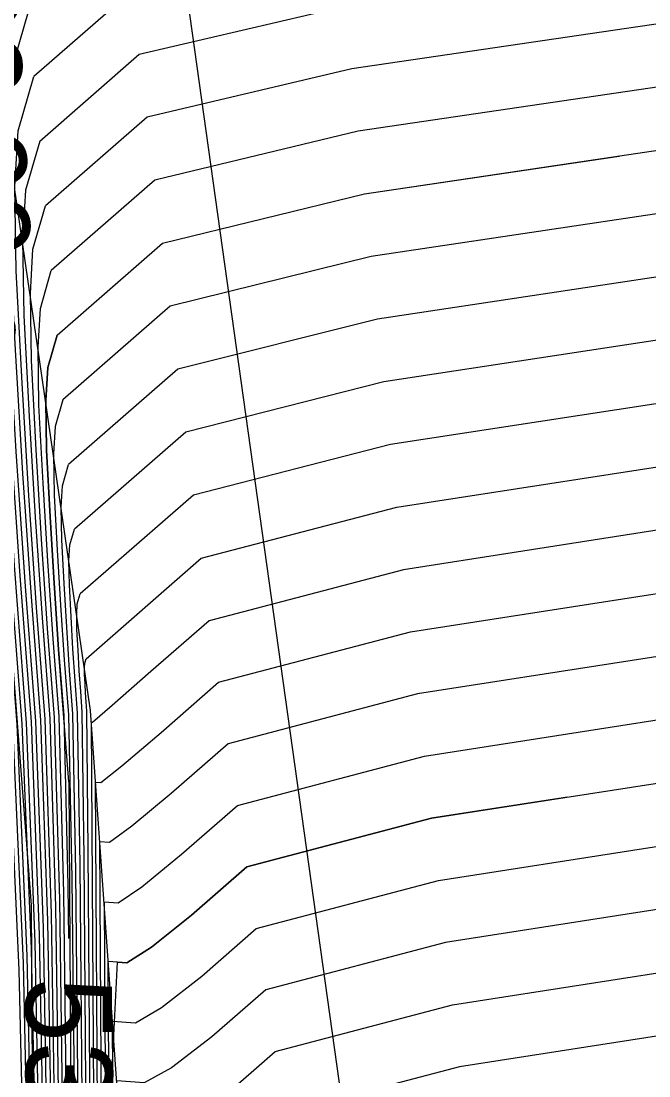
# Model space of a CAD drawing. Extents: x -866683 to -866410, y -1041951 to -1040252.
# Drawn here: x -866462.047 to -866459.87, y -1041930.1 to -1041926.441 of the extents above; entities that cross this region are included whole.
import ezdxf

# ---------------------------------------------------------------- set-up
doc = ezdxf.new("R2010")
doc.units = 0
for name, color, linetype in [('BODY', 7, 'Continuous'), ('BODY_2016', 7, 'Continuous'), ('BREAKLINE', 7, 'Continuous'), ('V-HL', 7, 'Continuous'), ('V-VEDL', 7, 'Continuous'), ('V_po_cm', 7, 'Continuous')]:
    doc.layers.add(name, color=color, linetype=linetype)

msp = doc.modelspace()

# ---------------------------------------------------------------- linework, layer by layer
at = {"layer": 'BREAKLINE'}
for points in [[(-866488.573, -1041881.791), (-866474.022, -1041889.87), (-866470.477, -1041891.508), (-866467.312, -1041894.734), (-866465.316, -1041898.37), (-866463.007, -1041915.39), (-866458.763, -1041945.697)], [(-866461.505, -1041933.103), (-866461.806, -1041928.832), (-866463.744, -1041915.502), (-866466.191, -1041900.225), (-866466.769, -1041897.87), (-866468.011, -1041895.26), (-866470.525, -1041893.498), (-866471.281, -1041892.954)]]:
    msp.add_lwpolyline(points, dxfattribs=at)
at = {"layer": 'V-HL'}
for points in [[(-866461.9223, -1041927.5304), (-866461.5568, -1041927.2112), (-866460.8556, -1041927.0405), (-866459.6359, -1041926.8588), (-866456.1597, -1041926.4733)], [(-866461.8819, -1041929.0798), (-866461.917, -1041928.6205), (-866461.9327, -1041928.3905), (-866461.9466, -1041928.1601), (-866461.9587, -1041927.9292), (-866461.9614, -1041927.7567), (-866461.9546, -1041927.6424), (-866461.9223, -1041927.5304)], [(-866461.8819, -1041929.0798), (-866461.8659, -1041931.7), (-866461.9581, -1041932.0447)]]:
    msp.add_lwpolyline(points, dxfattribs=at)
at = {"layer": 'V-VEDL'}
for points in [[(-866462.1228, -1041925.2864), (-866462.2109, -1041925.5913), (-866462.2293, -1041925.9026), (-866462.2221, -1041926.3727), (-866462.1891, -1041927.0015), (-866462.1512, -1041927.6293), (-866462.1084, -1041928.2559), (-866462.0127, -1041929.507)], [(-866465.5755, -1041931.3671), (-866464.7785, -1041933.0499), (-866464.3707, -1041933.5335), (-866463.9536, -1041933.6594), (-866463.5272, -1041933.4274), (-866463.09, -1041933.2561), (-866462.6419, -1041933.1454), (-866462.1831, -1041933.0953), (-866461.8794, -1041932.6906), (-866461.731, -1041931.9311), (-866461.7378, -1041930.817), (-866461.7316, -1041930.0749), (-866461.7123, -1041929.7051), (-866461.68, -1041929.7074), (-866461.5945, -1041929.6531), (-866461.4558, -1041929.5422), (-866461.264, -1041929.3746), (-866460.6237, -1041929.2061), (-866459.535, -1041929.0366), (-866456.4607, -1041928.6957)], [(-866462.0127, -1041929.507), (-866461.9986, -1041931.8189), (-866462.231, -1041932.6155), (-866462.7028, -1041933.0525), (-866463.4141, -1041933.1301), (-866463.92, -1041932.9596), (-866464.2206, -1041932.541), (-866464.3159, -1041931.8742), (-866464.3817, -1041931.5453), (-866464.4179, -1041931.5541), (-866464.4247, -1041931.9007), (-866464.5832, -1041931.8065), (-866464.8935, -1041931.2716), (-866465.8177, -1041929.3201)]]:
    msp.add_lwpolyline(points, dxfattribs=at)
at = {"layer": 'V_po_cm'}
for points in [[(-866448.9745, -1041923.5966), (-866449.3731, -1041923.7016), (-866450.158, -1041923.7067), (-866451.329, -1041923.6122), (-866452.8861, -1041923.4178), (-866453.9106, -1041923.4837), (-866454.4024, -1041923.8097), (-866454.3615, -1041924.3959), (-866454.3859, -1041924.9328), (-866454.4753, -1041925.4204), (-866454.63, -1041925.8587), (-866454.7785, -1041926.062), (-866454.9209, -1041926.0303), (-866455.057, -1041925.7635), (-866455.2418, -1041925.5954), (-866455.4752, -1041925.526), (-866455.7573, -1041925.5552), (-866456.5515, -1041925.6418), (-866457.8578, -1041925.786), (-866459.6763, -1041925.9876), (-866460.945, -1041926.1714), (-866461.664, -1041926.3371), (-866462.0025, -1041926.6328)], [(-866461.9824, -1041926.8572), (-866461.6372, -1041926.5556), (-866460.9226, -1041926.3886), (-866459.6662, -1041926.2054), (-866457.8678, -1041926.006), (-866456.5682, -1041925.8626), (-866455.7672, -1041925.7753), (-866455.465, -1041925.7441), (-866455.2149, -1041925.8185), (-866455.0169, -1041925.9986), (-866454.8711, -1041926.2844), (-866454.7186, -1041926.3184), (-866454.5595, -1041926.1006), (-866454.3937, -1041925.631), (-866454.2978, -1041925.1085), (-866454.2718, -1041924.5333), (-866454.3156, -1041923.9052), (-866453.8346, -1041923.5501), (-866452.8289, -1041923.4681), (-866451.2984, -1041923.6591), (-866450.1474, -1041923.7521), (-866449.376, -1041923.747), (-866448.9842, -1041923.6438)], [(-866448.9939, -1041923.691), (-866449.379, -1041923.7924), (-866450.1369, -1041923.7974), (-866451.2678, -1041923.7061), (-866452.7716, -1041923.5184), (-866453.7586, -1041923.6166), (-866454.2288, -1041924.0007), (-866454.182, -1041924.6706), (-866454.2098, -1041925.2842), (-866454.3121, -1041925.8415), (-866454.4889, -1041926.3424), (-866454.6586, -1041926.5747), (-866454.8213, -1041926.5385), (-866454.9769, -1041926.2336), (-866455.188, -1041926.0415), (-866455.4548, -1041925.9621), (-866455.7772, -1041925.9955), (-866456.5848, -1041926.0834), (-866457.8778, -1041926.226), (-866459.6561, -1041926.4232), (-866460.9003, -1041926.6059), (-866461.6104, -1041926.7741), (-866461.9624, -1041927.0816)], [(-866449.0037, -1041923.7382), (-866449.3819, -1041923.8378), (-866450.1264, -1041923.8427), (-866451.2372, -1041923.753), (-866452.7144, -1041923.5686), (-866453.6826, -1041923.683), (-866454.1419, -1041924.0961), (-866454.0923, -1041924.808), (-866454.1218, -1041925.4599), (-866454.2305, -1041926.052), (-866454.4183, -1041926.5842), (-866454.5986, -1041926.8311), (-866454.7715, -1041926.7926), (-866454.9368, -1041926.4687), (-866455.1612, -1041926.2645), (-866455.4446, -1041926.1802), (-866455.7871, -1041926.2156), (-866456.6015, -1041926.3042), (-866457.8878, -1041926.446), (-866459.646, -1041926.641), (-866460.8779, -1041926.8232), (-866461.5836, -1041926.9926), (-866461.9423, -1041927.306)], [(-866449.0232, -1041923.8327), (-866449.3877, -1041923.9286), (-866450.1053, -1041923.9334), (-866451.176, -1041923.8469), (-866452.5999, -1041923.6692), (-866453.5306, -1041923.8159), (-866453.9683, -1041924.2871), (-866453.9128, -1041925.0827), (-866453.9458, -1041925.8113), (-866454.0673, -1041926.4731), (-866454.2772, -1041927.0679), (-866454.4787, -1041927.3438), (-866454.6719, -1041927.3007), (-866454.8566, -1041926.9387), (-866455.1074, -1041926.7106), (-866455.4242, -1041926.6163), (-866455.807, -1041926.6559), (-866456.6349, -1041926.7458), (-866457.9078, -1041926.8861), (-866459.6258, -1041927.0766), (-866460.8332, -1041927.2578), (-866461.53, -1041927.4297), (-866461.9022, -1041927.7548)], [(-866449.0329, -1041923.8799), (-866449.3906, -1041923.9741), (-866450.0948, -1041923.9787), (-866451.1455, -1041923.8939), (-866452.5426, -1041923.7195), (-866453.4546, -1041923.8824), (-866453.8814, -1041924.3826), (-866453.8231, -1041925.22), (-866453.8578, -1041925.987), (-866453.9856, -1041926.6836), (-866454.2066, -1041927.3098), (-866454.4188, -1041927.6002), (-866454.6221, -1041927.5548), (-866454.8166, -1041927.1738), (-866455.0806, -1041926.9336), (-866455.414, -1041926.8344), (-866455.817, -1041926.8761), (-866456.6516, -1041926.9666), (-866457.9178, -1041927.1061), (-866459.6157, -1041927.2943), (-866460.8108, -1041927.475), (-866461.5031, -1041927.6482), (-866461.8822, -1041927.9793)], [(-866449.0426, -1041923.9271), (-866449.3935, -1041924.0195), (-866450.0843, -1041924.0241), (-866451.1149, -1041923.9408), (-866452.4854, -1041923.7698), (-866453.3786, -1041923.9488), (-866453.7946, -1041924.478), (-866453.7333, -1041925.3574), (-866453.7698, -1041926.1628), (-866453.904, -1041926.8942), (-866454.136, -1041927.5516), (-866454.3588, -1041927.8565), (-866454.5723, -1041927.8089), (-866454.7765, -1041927.4088), (-866455.0537, -1041927.1567), (-866455.4038, -1041927.0525), (-866455.8269, -1041927.0963), (-866456.6682, -1041927.1875), (-866457.9278, -1041927.3261), (-866459.6056, -1041927.5121), (-866460.7885, -1041927.6923), (-866461.4763, -1041927.8667), (-866461.8621, -1041928.2037)], [(-866449.0524, -1041923.9743), (-866449.3964, -1041924.0649), (-866450.0737, -1041924.0694), (-866451.0843, -1041923.9878), (-866452.4282, -1041923.82), (-866453.3026, -1041924.0153), (-866453.7078, -1041924.5735), (-866453.6436, -1041925.4947), (-866453.6818, -1041926.3385), (-866453.8224, -1041927.1047), (-866454.0655, -1041927.7934), (-866454.2988, -1041928.1129), (-866454.5225, -1041928.063), (-866454.7364, -1041927.6439), (-866455.0268, -1041927.3797), (-866455.3936, -1041927.2706), (-866455.8369, -1041927.3164), (-866456.6849, -1041927.4083), (-866457.9378, -1041927.5461), (-866459.5955, -1041927.7299), (-866460.7661, -1041927.9096), (-866461.4495, -1041928.0852), (-866461.8421, -1041928.4281)], [(-866461.822, -1041928.6525), (-866461.4227, -1041928.3037), (-866460.7437, -1041928.1269), (-866459.5854, -1041927.9477), (-866457.9478, -1041927.7661), (-866456.7016, -1041927.6291), (-866455.8468, -1041927.5366), (-866455.3834, -1041927.4886), (-866454.9999, -1041927.6027), (-866454.6964, -1041927.8789), (-866454.4727, -1041928.3171), (-866454.2389, -1041928.3692), (-866453.9949, -1041928.0353), (-866453.7408, -1041927.3152), (-866453.5938, -1041926.5142), (-866453.5538, -1041925.6321), (-866453.621, -1041924.669), (-866453.2267, -1041924.0817), (-866452.3709, -1041923.8703), (-866451.0537, -1041924.0347), (-866450.0632, -1041924.1147), (-866449.3993, -1041924.1103), (-866449.0621, -1041924.0215)], [(-866461.7885, -1041929.0808), (-866461.77, -1041929.0821), (-866461.6974, -1041929.0245), (-866461.5614, -1041928.9087), (-866461.3621, -1041928.7345), (-866460.6967, -1041928.5594), (-866459.5653, -1041928.3833), (-866457.9678, -1041928.2061), (-866456.735, -1041928.0707), (-866455.8667, -1041927.9769), (-866455.363, -1041927.9248), (-866454.9462, -1041928.0488), (-866454.6162, -1041928.349), (-866454.3731, -1041928.8253), (-866454.119, -1041928.8819), (-866453.8538, -1041928.5189), (-866453.5776, -1041927.7363), (-866453.4177, -1041926.8656), (-866453.3743, -1041925.9068), (-866453.4473, -1041924.86), (-866453.0747, -1041924.2146), (-866452.2564, -1041923.9709)], [(-866453.1507, -1041924.1482), (-866453.5341, -1041924.7645), (-866453.4641, -1041925.7694), (-866453.5057, -1041926.6899), (-866453.6592, -1041927.5257), (-866453.9243, -1041928.2771), (-866454.1789, -1041928.6256), (-866454.4229, -1041928.5712), (-866454.6563, -1041928.1139), (-866454.9731, -1041927.8258), (-866455.3732, -1041927.7067), (-866455.8568, -1041927.7567), (-866456.7183, -1041927.8499), (-866457.9578, -1041927.9861), (-866459.5754, -1041928.1655), (-866460.721, -1041928.3438), (-866461.3947, -1041928.5212), (-866461.5966, -1041928.6975), (-866461.7317, -1041928.815), (-866461.8, -1041928.8737), (-866461.8031, -1041928.8735)], [(-866462.1629, -1041924.8375), (-866462.2622, -1041925.1811), (-866462.2829, -1041925.5318), (-866462.2747, -1041926.0614), (-866462.2376, -1041926.7698), (-866462.1949, -1041927.477), (-866462.1467, -1041928.183), (-866462.0928, -1041928.8877), (-866462.0546, -1041929.7326), (-866462.032, -1041930.7176), (-866462.0251, -1041931.8427), (-866462.2513, -1041932.618), (-866462.7106, -1041933.0434), (-866463.4028, -1041933.1189), (-866463.9039, -1041932.8928), (-866464.2137, -1041932.3651), (-866464.4508, -1041930.7064)], [(-866462.1428, -1041925.062), (-866462.2365, -1041925.3862), (-866462.2561, -1041925.7172), (-866462.2484, -1041926.217), (-866462.2134, -1041926.8857), (-866462.1731, -1041927.5532), (-866462.1275, -1041928.2195), (-866462.0767, -1041928.8846), (-866462.0404, -1041929.7082), (-866462.0188, -1041930.6903), (-866462.0119, -1041931.8308), (-866462.2411, -1041932.6167), (-866462.7067, -1041933.048), (-866463.4084, -1041933.1245), (-866463.9119, -1041932.9262), (-866464.2171, -1041932.453), (-866464.431, -1041930.957)], [(-866462.1027, -1041925.5108), (-866462.1853, -1041925.7964), (-866462.2025, -1041926.088), (-866462.1957, -1041926.5283), (-866462.1649, -1041927.1174), (-866462.1294, -1041927.7054), (-866462.0892, -1041928.2924), (-866462.0444, -1041928.8783), (-866462.0122, -1041929.6594), (-866461.9925, -1041930.6357), (-866461.9853, -1041931.807), (-866462.2208, -1041932.6142), (-866462.6989, -1041933.0571), (-866463.4197, -1041933.1357), (-866463.928, -1041932.993), (-866464.2241, -1041932.6289), (-866464.3914, -1041931.4581)], [(-866464.3716, -1041931.7086), (-866464.2275, -1041932.7168), (-866463.9361, -1041933.0263), (-866463.4253, -1041933.1413), (-866462.695, -1041933.0616), (-866462.2106, -1041932.6129), (-866461.9721, -1041931.7951), (-866461.9793, -1041930.6083), (-866461.9981, -1041929.635), (-866462.0283, -1041928.8752), (-866462.0701, -1041928.3288), (-866462.1075, -1041927.7815), (-866462.1406, -1041927.2332), (-866462.1694, -1041926.684), (-866462.1757, -1041926.2734), (-866462.1597, -1041926.0015), (-866462.0827, -1041925.7352)], [(-866462.0626, -1041925.9596), (-866462.134, -1041926.2066), (-866462.1489, -1041926.4588), (-866462.1431, -1041926.8396), (-866462.1164, -1041927.3491), (-866462.0857, -1041927.8576), (-866462.051, -1041928.3653), (-866462.0122, -1041928.8721), (-866461.9839, -1041929.6106), (-866461.9661, -1041930.581), (-866461.9588, -1041931.7833), (-866462.2005, -1041932.6116), (-866462.6911, -1041933.0662), (-866463.4309, -1041933.1469), (-866463.9441, -1041933.0597), (-866464.231, -1041932.8048), (-866464.3519, -1041931.9592)], [(-866464.3321, -1041932.2097), (-866464.2345, -1041932.8927), (-866463.9522, -1041933.0931), (-866463.4365, -1041933.1525), (-866462.6873, -1041933.0707), (-866462.1903, -1041932.6104), (-866461.9455, -1041931.7714), (-866461.9529, -1041930.5537), (-866461.9698, -1041929.5863), (-866461.9961, -1041928.8689), (-866462.0318, -1041928.4018), (-866462.0638, -1041927.9338), (-866462.0921, -1041927.4649), (-866462.1167, -1041926.9953), (-866462.1221, -1041926.6442), (-866462.1084, -1041926.4118), (-866462.0426, -1041926.184)], [(-866462.0225, -1041926.4084), (-866462.0828, -1041926.6169), (-866462.0954, -1041926.8296), (-866462.0904, -1041927.1509), (-866462.0679, -1041927.5808), (-866462.042, -1041928.0099), (-866462.0127, -1041928.4382), (-866461.98, -1041928.8658), (-866461.9557, -1041929.5619), (-866461.9398, -1041930.5264), (-866461.9322, -1041931.7595), (-866462.1801, -1041932.6091), (-866462.6834, -1041933.0753), (-866463.4421, -1041933.158), (-866463.9602, -1041933.1265), (-866464.2379, -1041932.9806), (-866464.3123, -1041932.4602)], [(-866464.2925, -1041932.7108), (-866464.2414, -1041933.0686), (-866463.9683, -1041933.1599), (-866463.4477, -1041933.1636), (-866462.6795, -1041933.0798), (-866462.1699, -1041932.6078), (-866461.919, -1041931.7476), (-866461.9266, -1041930.4991), (-866461.9416, -1041929.5375), (-866461.9639, -1041928.8627), (-866461.9936, -1041928.4747), (-866462.0201, -1041928.086), (-866462.0436, -1041927.6966), (-866462.0641, -1041927.3066), (-866462.0686, -1041927.015), (-866462.0572, -1041926.822), (-866462.0025, -1041926.6328)], [(-866461.9824, -1041926.8572), (-866462.0315, -1041927.0271), (-866462.0418, -1041927.2004), (-866462.0377, -1041927.4622), (-866462.0194, -1041927.8125), (-866461.9983, -1041928.1621), (-866461.9744, -1041928.5111), (-866461.9478, -1041928.8595), (-866461.9274, -1041929.5131), (-866461.9134, -1041930.4718), (-866461.9057, -1041931.7357), (-866462.1598, -1041932.6065), (-866462.6756, -1041933.0844), (-866463.4533, -1041933.1692), (-866463.9763, -1041933.1933), (-866464.2448, -1041933.1565), (-866464.2727, -1041932.9613)], [(-866461.9223, -1041927.5304), (-866461.5568, -1041927.2112), (-866460.8556, -1041927.0405), (-866459.9725, -1041926.9089)], [(-866464.253, -1041933.2119), (-866464.2483, -1041933.2444), (-866463.9844, -1041933.2266), (-866463.4589, -1041933.1748), (-866462.6717, -1041933.0889), (-866462.1496, -1041932.6053), (-866461.8924, -1041931.7238), (-866461.9002, -1041930.4445), (-866461.9133, -1041929.4887), (-866461.9317, -1041928.8564), (-866461.9553, -1041928.5476), (-866461.9764, -1041928.2382), (-866461.9951, -1041927.9283), (-866462.0114, -1041927.6179), (-866462.015, -1041927.3858), (-866462.0059, -1041927.2322), (-866461.9624, -1041927.0816)], [(-866464.2579, -1041933.3047), (-866464.2001, -1041933.2732), (-866463.9252, -1041933.2349), (-866463.4045, -1041933.1739), (-866462.6379, -1041933.0902), (-866462.1294, -1041932.6029), (-866461.8791, -1041931.7119), (-866461.8871, -1041930.4172), (-866461.8992, -1041929.4643), (-866461.9156, -1041928.8533), (-866461.9361, -1041928.5841), (-866461.9546, -1041928.3144), (-866461.9709, -1041928.0442), (-866461.9851, -1041927.7736), (-866461.9882, -1041927.5712), (-866461.9803, -1041927.4373), (-866461.9423, -1041927.306)], [(-866461.9223, -1041927.5304), (-866461.9546, -1041927.6424), (-866461.9614, -1041927.7567), (-866461.9587, -1041927.9292), (-866461.9466, -1041928.1601), (-866461.9327, -1041928.3905), (-866461.917, -1041928.6205), (-866461.8994, -1041928.8502), (-866461.8851, -1041929.4399), (-866461.8829, -1041929.6233)], [(-866461.9022, -1041927.7548), (-866461.929, -1041927.8475), (-866461.9346, -1041927.9421), (-866461.9324, -1041928.0849), (-866461.9224, -1041928.2759), (-866461.9109, -1041928.4666), (-866461.8979, -1041928.657), (-866461.8833, -1041928.847), (-866461.8709, -1041929.4156), (-866461.8607, -1041930.3626), (-866461.8526, -1041931.6881), (-866462.0841, -1041932.5976), (-866462.5552, -1041933.0912), (-866463.2659, -1041933.1687), (-866463.7734, -1041933.2387), (-866464.0777, -1041933.3013), (-866464.2801, -1041933.4113)], [(-866464.2912, -1041933.4647), (-866464.0166, -1041933.3153), (-866463.6974, -1041933.2406), (-866463.1965, -1041933.1661), (-866462.5138, -1041933.0916), (-866462.0614, -1041932.595), (-866461.8393, -1041931.6762), (-866461.8475, -1041930.3353), (-866461.8568, -1041929.3912), (-866461.8672, -1041928.8439), (-866461.8787, -1041928.6934), (-866461.889, -1041928.5427), (-866461.8981, -1041928.3918), (-866461.9061, -1041928.2405), (-866461.9078, -1041928.1275), (-866461.9034, -1041928.0526), (-866461.8822, -1041927.9793)], [(-866462.046, -1041931.9815), (-866461.9986, -1041931.8189), (-866462.0057, -1041930.663), (-866462.0263, -1041929.6838), (-866462.0606, -1041928.8814), (-866462.1084, -1041928.2559), (-866462.1254, -1041928.007)], [(-866454.5761, -1041928.584), (-866454.9193, -1041928.2718), (-866455.3528, -1041928.1428), (-866455.8767, -1041928.197), (-866456.7517, -1041928.2915), (-866457.9778, -1041928.4261), (-866459.5552, -1041928.601), (-866460.6723, -1041928.775), (-866461.3294, -1041928.9479), (-866461.5262, -1041929.1198), (-866461.6631, -1041929.234), (-866461.74, -1041929.2906), (-866461.7739, -1041929.2881)], [(-866464.3023, -1041933.518), (-866463.9554, -1041933.3293), (-866463.6215, -1041933.2426), (-866463.1272, -1041933.1635), (-866462.4725, -1041933.0921), (-866462.0388, -1041932.5924), (-866461.8261, -1041931.6643), (-866461.8343, -1041930.308), (-866461.8427, -1041929.3668), (-866461.8511, -1041928.8408), (-866461.8596, -1041928.7299), (-866461.8672, -1041928.6189), (-866461.8739, -1041928.5076), (-866461.8797, -1041928.3962), (-866461.881, -1041928.3129), (-866461.8778, -1041928.2577), (-866461.8621, -1041928.2037)], [(-866461.7592, -1041929.4955), (-866461.71, -1041929.499), (-866461.6288, -1041929.4436), (-866461.491, -1041929.331), (-866461.2967, -1041929.1613), (-866460.648, -1041928.9905), (-866459.5451, -1041928.8188), (-866457.9878, -1041928.6461), (-866456.7683, -1041928.5123), (-866455.8866, -1041928.4172), (-866455.3426, -1041928.3609), (-866454.8924, -1041928.4949), (-866454.5361, -1041928.819)], [(-866464.3134, -1041933.5713), (-866463.8942, -1041933.3433), (-866463.5456, -1041933.2445), (-866463.0579, -1041933.1609), (-866462.4311, -1041933.0926), (-866462.0161, -1041932.5897), (-866461.8128, -1041931.6524), (-866461.8212, -1041930.2807), (-866461.8286, -1041929.3424), (-866461.835, -1041928.8376), (-866461.8404, -1041928.7664), (-866461.8453, -1041928.695), (-866461.8496, -1041928.6235), (-866461.8534, -1041928.5518), (-866461.8542, -1041928.4983), (-866461.8521, -1041928.4628), (-866461.8421, -1041928.4281)], [(-866464.3245, -1041933.6247), (-866463.8331, -1041933.3573), (-866463.4696, -1041933.2464), (-866462.9886, -1041933.1583), (-866462.3898, -1041933.093), (-866461.9935, -1041932.5871), (-866461.7995, -1041931.6405), (-866461.808, -1041930.2533), (-866461.8144, -1041929.318), (-866461.8189, -1041928.8345), (-866461.8213, -1041928.8028), (-866461.8235, -1041928.7711), (-866461.8254, -1041928.7393), (-866461.8271, -1041928.7075), (-866461.8274, -1041928.6837), (-866461.8265, -1041928.6679), (-866461.822, -1041928.6525)], [(-866461.73, -1041929.9101), (-866461.65, -1041929.9158), (-866461.5602, -1041929.8626), (-866461.4206, -1041929.7533), (-866461.2313, -1041929.588), (-866460.5994, -1041929.4217), (-866459.5249, -1041929.2544), (-866458.0078, -1041929.0862), (-866456.8017, -1041928.9539), (-866455.9065, -1041928.8575), (-866455.3222, -1041928.797), (-866454.8387, -1041928.9409)], [(-866464.3356, -1041933.678), (-866463.7719, -1041933.3713), (-866463.3937, -1041933.2484), (-866462.9192, -1041933.1558), (-866462.3485, -1041933.0935), (-866461.9708, -1041932.59), (-866461.7861, -1041931.6453), (-866461.8031, -1041928.8735)], [(-866454.8118, -1041929.164), (-866455.312, -1041929.0151), (-866455.9164, -1041929.0776), (-866456.8184, -1041929.1747), (-866458.0178, -1041929.3062), (-866459.5148, -1041929.4722), (-866460.5751, -1041929.6372), (-866461.1986, -1041929.8013), (-866461.3854, -1041929.9645), (-866461.5259, -1041930.0722), (-866461.6199, -1041930.1243), (-866461.7154, -1041930.1174)], [(-866464.3467, -1041933.7313), (-866463.7107, -1041933.3854), (-866463.3178, -1041933.2503), (-866462.8499, -1041933.1532), (-866462.3071, -1041933.094), (-866461.9479, -1041932.6151), (-866461.7724, -1041931.7168), (-866461.7885, -1041929.0808)], [(-866460.1515, -1041929.1326), (-866460.6237, -1041929.2061), (-866461.264, -1041929.3746), (-866461.4558, -1041929.5422), (-866461.5945, -1041929.6531), (-866461.68, -1041929.7074), (-866461.7446, -1041929.7028)], [(-866461.7008, -1041930.3248), (-866461.5899, -1041930.3327), (-866461.4915, -1041930.2817), (-866461.3502, -1041930.1757), (-866461.1659, -1041930.0147), (-866460.5507, -1041929.8528), (-866459.5047, -1041929.69), (-866458.0278, -1041929.5262), (-866456.8351, -1041929.3955), (-866455.9264, -1041929.2978), (-866455.3018, -1041929.2332), (-866454.785, -1041929.387)], [(-866464.3578, -1041933.7847), (-866463.6496, -1041933.3994), (-866463.2419, -1041933.2522), (-866462.7806, -1041933.1506), (-866462.2658, -1041933.0944), (-866461.9251, -1041932.6403), (-866461.7586, -1041931.7882), (-866461.7739, -1041929.2881)], [(-866454.7581, -1041929.61), (-866455.2916, -1041929.4513), (-866455.9363, -1041929.518), (-866456.8517, -1041929.6163), (-866458.0378, -1041929.7462), (-866459.4946, -1041929.9077), (-866460.5264, -1041930.0684), (-866461.1332, -1041930.2281), (-866461.315, -1041930.3869), (-866461.4572, -1041930.4912), (-866461.5599, -1041930.5411), (-866461.6862, -1041930.5321)], [(-866461.7592, -1041929.4955), (-866461.7448, -1041931.8597), (-866461.9023, -1041932.6654), (-866462.2244, -1041933.0949), (-866462.7113, -1041933.148), (-866463.1659, -1041933.2542), (-866463.5884, -1041933.4134), (-866464.3689, -1041933.838)], [(-866464.38, -1041933.8913), (-866463.5272, -1041933.4274), (-866463.09, -1041933.2561), (-866462.6419, -1041933.1454), (-866462.1831, -1041933.0953), (-866461.8794, -1041932.6906), (-866461.731, -1041931.9311), (-866461.7446, -1041929.7028)], [(-866464.3912, -1041933.9447), (-866463.466, -1041933.4414), (-866463.0141, -1041933.258), (-866462.5726, -1041933.1428), (-866462.1417, -1041933.0958), (-866461.8566, -1041932.7157), (-866461.7172, -1041932.0026), (-866461.73, -1041929.9101)]]:
    msp.add_lwpolyline(points, dxfattribs=at)

# ---------------------------------------------------------------- texts
at = {"layer": 'BODY'}
msp.add_text('+', height=0.001, rotation=360, dxfattribs=at).set_placement((-866461.806, -1041928.832))
at = {"layer": 'BODY_2016'}
msp.add_text('+', height=0.001, rotation=360, dxfattribs=at).set_placement((-866461.806, -1041928.832))
at = {"layer": 'V_po_cm'}
for s, rotation, p in [('532.90m', 272.8334, (-866462.3726, -1041926.0469)), ('533.00m', 270.2964, (-866462.0322, -1041929.7591))]:
    msp.add_text(s, height=0.3, rotation=rotation, dxfattribs=at).set_placement(p)

doc.saveas('drawing.dxf')
